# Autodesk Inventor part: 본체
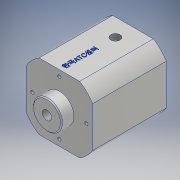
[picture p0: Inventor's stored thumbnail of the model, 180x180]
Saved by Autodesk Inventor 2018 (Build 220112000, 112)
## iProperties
Created: 2020-02
Part Number: 본체
Material: 알루미늄 6061
Document SubType Name: Modeling
Designer: USER
Density: 2.7 g/cm^3
Appearance: 알루미늄 - 평지
Mass: 537.891 g
Surface Area: 342.742 cm^2
Volume: 199.219 cm^3
Author: USER
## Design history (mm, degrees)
sketch "스케치1"
  geometry: L1 (19.551, 32)-(-19.551, 32); L2 (-32, 19.551)-(-32, -19.551); L3 (32, -19.551)-(32, 19.551); L4 (32, 32)-(-32, -32); L5 (-32, 32)-(32, -32); L6 (-19.551, -32)-(19.551, -32); A1 r 37.5 centre (0, 0) between (32, 19.551) and (19.551, 32); A2 r 37.5 centre (0, 0) between (-19.551, 32) and (-32, 19.551); A3 r 37.5 centre (0, 0) between (-32, -19.551) and (-19.551, -32); A4 r 37.5 centre (0, 0) between (19.551, -32) and (32, -19.551); 5 further points
  constraints: 12 end point, 8 point on circle, 6 midpoint, 4 centre point, 3 parallel, 2 horizontal, 2 vertical alignment, 1 coincident, 1 perpendicular
  dimensions: "d3" = 64 distance between parallel lines of L6 L1; "d4" = 64 distance between parallel lines of L2 L3; "d5" = 37.5 radius of A2; "d6" = 37.5 radius of A1; "d7" = 37.5 radius of A4; "d8" = 37.5 radius of A3
extrude "돌출1" new body sketch "스케치1" distance "d9" = 71; taper "d10" = 0 deg
sketch "스케치2"
  geometry: C1 r 14 at (0, 0); 1 further point
  constraints: 1 centre point, 1 coincident
  dimensions: "d11" = 28 diameter of C1
extrude "돌출2" join sketch "스케치2" distance "d12" = 12; taper "d13" = 0 deg
sketch "스케치3"
  geometry: C1 r 14 at (0, 0) reference; 2 further points
  constraints: 1 coincident
hole "구멍1" sketch "스케치3" at (0, 0) diameter "d14" = 8.917; stored, may be unused: countersink angle "d18" = 90 deg, drill point angle "d20" = 118 deg; dims "d15" = 14, "d16" = 4, "d17" = 2, "d19" = 17
sketch "스케치4"
  geometry: C1 r 14 at (0, 0) reference; A1 r 26 centre (0, 0) between (0, 26) and (26, 0); 3 further points
  constraints: 4 point on circle, 2 horizontal alignment, 2 vertical alignment, 1 centre point, 1 coincident
  dimensions: "d21" = 52 diameter of A1
hole "구멍2" sketch "스케치4" at (0, 26), (26, 0), (0, -26), (-26, 0) diameter "d22" = 3.242; stored, may be unused: countersink angle "d26" = 90 deg, drill point angle "d28" = 118 deg; dims "d23" = 10, "d24" = 4, "d25" = 2, "d27" = 12
sketch "스케치5"
  geometry: L1 (0, 0)-(39.102, 0) reference; 3 further points
  constraints: 1 midpoint, 1 vertical alignment, 1 other
  dimensions: "d29" = 20 distance from line of L1 point (19.551, 20)
feature "엠보싱1" sketch "스케치5" dims "d3" = 64, "d4" = 64, "d5" = 37.5, "d6" = 37.5, "d7" = 37.5, "d8" = 37.5, "d30" = 0.5, "d31" = 0
sketch "스케치6"
  geometry: L1 (0, 71)-(39.102, 71) reference; L2 (0, 0)-(39.102, 0) reference; 3 further points
  constraints: 1 midpoint, 1 vertical alignment
  dimensions: "d32" = 17 distance from line of L1 point (19.551, 54)
hole "구멍3" sketch "스케치6" at (19.551, 54) diameter "d33" = 8.917; stored, may be unused: countersink angle "d37" = 90 deg, drill point angle "d39" = 118 deg; dims "d34" = 6, "d35" = 4, "d36" = 2, "d38" = 9
sketch "스케치7"
  geometry: C1 r 20 at (0, 0); 1 further point
  constraints: 1 centre point, 1 coincident
  dimensions: "d40" = 40 diameter of C1
extrude "돌출3" cut sketch "스케치7" distance "d41" = 62; taper "d42" = 0 deg
sketch "스케치8"
  geometry: C1 r 2 at (0, 0); 1 further point
  constraints: 1 centre point, 1 coincident
  dimensions: "d43" = 4 diameter of C1
extrude "돌출4" cut sketch "스케치8" distance "d44" = 7; taper "d45" = 0 deg
sketch "스케치9"
  geometry: 1 further point
node "작업 평면1"
sketch "스케치10"
  geometry: L1 (-20, 0)-(20, 0) reference; L2 (19.551, -71)-(-19.551, -71) reference; C1 r 2 at (0, -17); 2 further points
  constraints: 1 centre point, 1 midpoint, 1 vertical alignment
  dimensions: "d46" = 4 diameter of C1; "d47" = 17 distance from line of C1.centre L1
extrude "돌출5" cut sketch "스케치10" distance "d48" = 3; taper "d49" = 0 deg
sketch "스케치11"
  geometry: 1 further point
sketch "스케치12"
  geometry: L1 (0, -19)-(0, -15) reference; C1 r 2 at (0, -17); 1 further point
  constraints: 1 centre point, 1 midpoint
  dimensions: "d50" = 4 diameter of C1
extrude "돌출6" cut sketch "스케치12" distance "d51" = 3; taper "d52" = 0 deg
sketch "스케치13"
  geometry: C1 r 20 at (0, 0) reference; C2 r 2 at (0, 0) reference; C3 r 26 at (0, 0); C4 r 1.621 at (0, 26) reference; 5 further points
  constraints: 4 coincident, 1 centre point, 4 other
  dimensions: "d53" = 52 diameter of C3; "d56" = 360 deg dimension on C3.centre point (0, 26) (derived)
hole "구멍4" sketch "스케치13" at (-22.517, -13), (22.517, -13), (0, 26) diameter "d58" = 3.242; stored, may be unused: countersink angle "d62" = 90 deg, drill point angle "d64" = 118 deg; dims "d59" = 10, "d60" = 4, "d61" = 2, "d63" = 12
chamfer "모따기1" distance "d65" = 1.8; stored, may be unused: second distance "d66" = 2, angle "d67" = 15 deg
sketch "스케치14"
  geometry: 1 further point
chamfer "모따기2" distance "d68" = 1; stored, may be unused: second distance "d69" = 2, angle "d70" = 45 deg
node "솔리드1"
node "투영된 루프1"
other parameters: "d0" = 75
